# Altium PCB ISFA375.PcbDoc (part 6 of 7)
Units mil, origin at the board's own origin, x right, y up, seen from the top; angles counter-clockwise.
Board outline 5615 x 5520 mil, 6 copper layers (Top_SL, GND, POWER, Signal_Layer, GND2, Bottom_SL), stack 60.472 mil thick; 494 components, 307 nets, 1648 pads, 755 vias.
Unrouted connection lines stored in the file: 315.
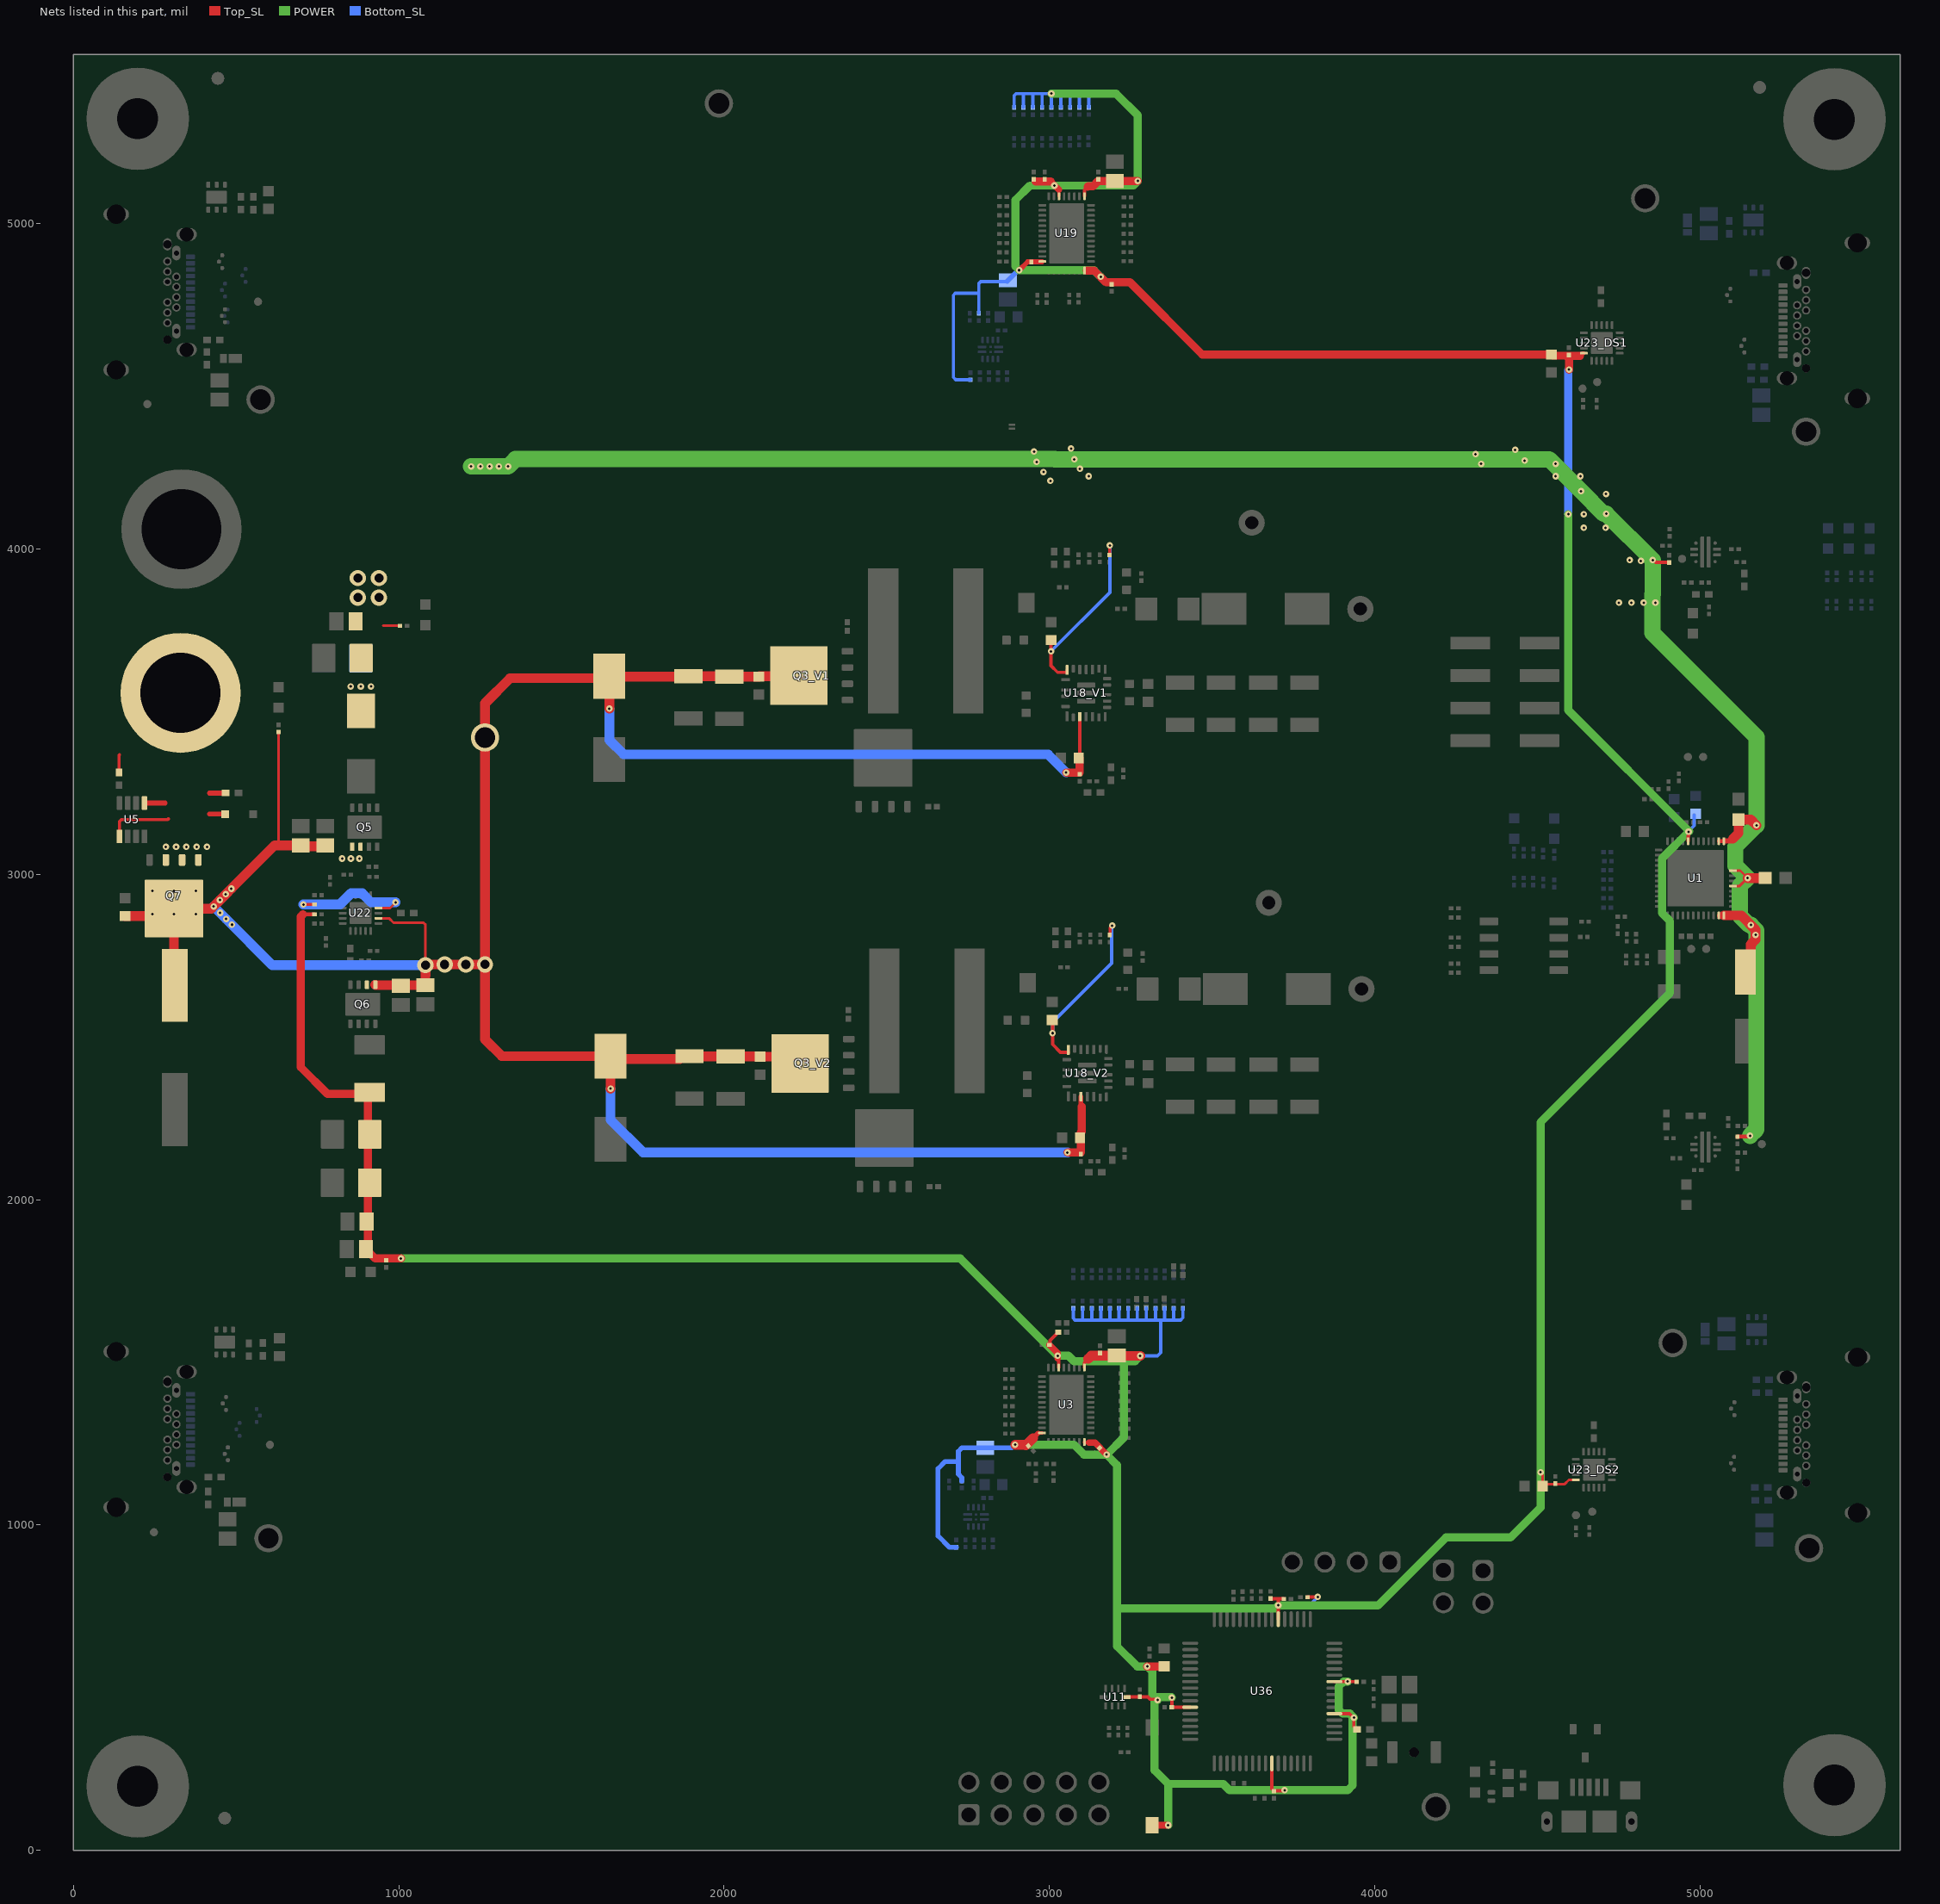
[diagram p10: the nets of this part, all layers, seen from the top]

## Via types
v1: diameter 20, hole 8, Top_SL to Bottom_SL, 628 vias
v2: diameter 19.68, hole 7.87, Top_SL to Bottom_SL, 66 vias
v3: diameter 16, hole 8, Top_SL to Bottom_SL, 23 vias
v4: diameter 16, hole 6, Top_SL to Bottom_SL, tented both sides, 16 vias
v5: diameter 137.8, hole 125.98, Top_SL to Bottom_SL, 8 vias
v6: diameter 50, hole 28, Top_SL to Bottom_SL, 8 vias
v7: diameter 28, hole 16, Top_SL to Bottom_SL, 6 vias

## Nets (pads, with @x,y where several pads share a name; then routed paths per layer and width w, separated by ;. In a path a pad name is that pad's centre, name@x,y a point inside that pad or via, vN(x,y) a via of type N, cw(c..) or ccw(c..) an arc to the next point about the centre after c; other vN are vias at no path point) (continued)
VCC_3.3V: C4.1 C13.1 C14.1 C15.1 C16.1 C17.1 C36.1 C59.1 C60.1 C61.1 C62.1 C63.1 C92.1 C93.1 C96.1 C97.1 C105.1 C106.1 C107.1 C116.1 C122_DS1.1 C122_DS2.1 L4_USB1.1 L4_USB2.1 L8.2 R23.2 R29.2 R33.2 R34.2 R35.2 R36.2 R37.2 R38.2 R39.2 R40.2 R41.2 R42.2 R43.2 R44.2 R50.2 R78.1 R79.2 R80.2 R81.2 R82.2 R83.2 R84.2 R85.2 R86.2 R87.2 R90_USB1.2 R90_USB2.2 R103_USB1.1 R103_USB2.1 R116.2 R125.2 R126.2 R127.1 R163_DS1.1 R163_DS2.1 S1.1 U1.32 U3.1 U3.6 U3.20 U3.28 U11.10 U19.1 U19.6 U19.20 U19.28 U23_DS1.10 U23_DS2.10 U36.11 U36.26 U36.37 U36.42 U36.54 | length 19780
  Top_SL w6: U19.20@2977.23,4882.9 U19.20@2978.16,4883.83
  Top_SL w8: v1(4509.98,1162.44) 4509.98,1159.19 4515.89,1153.29 C122_DS2.1@4515.89,1119.81 4522.19,1126.11 R163_DS2.1@4554.97,1126.11 ; R163_DS2.1@4554.97,1127.49 4556.35,1126.11 4584.11,1126.11 4596.83,1138.83 U23_DS2.10@4618.56,1138.83
  Top_SL w10: U3.20@2965.9,1282.43 2966.59,1283.12 U3.20@2977.43,1283.12 ; C14.1@3000.14,1553.59 3000.28,1553.59 3001.77,1555.08 3001.77,1567.58 3023.13,1588.94 3023.13,1589.73 3026.4,1593 R37.2@3027.19,1593 ; v1@3025.36,1512.36 3028.61,1509.11 U3.6@3028.61,1483.91 ; U19.6@3029.35,5084.62 3029.35,5104.68 ; U3.28@3107.35,1255.56 3107.35,1254.13 3108.42,1253.06 3121.5,1253.06 ; U3.1@3107.35,1483.91 3107.35,1499.23 3119.17,1511.04 ; U19.1@3108.09,5084.62 3108.09,5103.95 3117.89,5113.76 ; U11.10@3237.44,470.96 3238.08,471.6 3277.16,471.6 C116.1@3277.8,472.24 3278.12,471.92 3302.69,471.92 3310.34,464.27 3330.78,464.27 v1(3332.69,462.36) ; v1(3376.32,469.51) C107.1@3376.32,439.98 U36.11@3432.9,439.98 ; U36.26@3683.89,267.74 3683.89,189.18 3690.21,182.86 C106.1@3690.21,182.24 ; C105.1@3684.99,771.75 3680.86,771.75 3679.56,773.05 C105.1@3679.56,773.84 3703.57,773.83 ; C106.1@3690.21,182.07 C106.1@3690.21,182.24 ; U36.54@3703.57,710.65 3703.57,773.83 ; R126.2@3720.83,772.86 3719.86,773.83 3703.57,773.83 ; v1(3723.26,185) 3721.79,183.54 3691.51,183.54 C106.1@3690.21,182.24 ; R125.2@3793.41,778.37 3793.71,778.66 3824.56,778.66 v1(3824.85,778.96) ; U36.37@3875.82,420.3 3922.61,420.3 3935.04,407.86 v1(3935.83,407.86) 3935.83,379.9 3943.66,372.07 R127.1@3945.63,372.07 ; U36.42@3875.82,518.72 3875.89,518.8 3916.8,518.8 v1(3917,519) 3917.34,518.66 3944.06,518.66 C36.1@3944.4,518.32 ; U1.32@4963.38,3102.17 4963.38,3117.14 4964.72,3118.48 4964.72,3130.81 v1(4964.78,3130.88)
  Top_SL w12: 705.64,2877.58 R23.2@740.59,2877.58 ; 4631.23,4594 4639.1,4601.88 U23_DS1.10@4642.85,4601.88
  Top_SL w15: v1(2907.3,4857.23) 2932.97,4882.9 U19.20@2977.23,4882.9 ; 2949.9,1267.12 2965.21,1282.43 U3.20@2965.9,1282.43
  Top_SL w20: C14.1@3000.14,1553.59 3025.36,1528.37 v1(3025.36,1520.37) v1@3025.36,1512.36 ; 3004.06,5129.97 3029.35,5104.68 ; 3121.5,1253.06 3140.18,1253.06 v1@3176.35,1216.89 ; S1.1@3316.08,77.38 v1(3365.29,77.38)
  Top_SL w25: 705.64,2877.58 698.61,2870.55 698.61,2407.39 780.95,2325.05 905.28,2325.05 905.28,1854.17 C97.1@899.14,1848.03 927.68,1819.49 v1(1006.61,1819.49) ; C60.1@2957.4,5129.97 3004.06,5129.97 ; 3115,4856 3137.94,4856 3174.19,4819.75 3248,4819.75 3470.01,4597.74 C122_DS1.1@4543.49,4597.74 4546.73,4594.49 4587,4594.49 4587.49,4594 R163_DS1.1@4597.08,4594 ; 3117.89,5113.76 3119.21,5115.07 3133.61,5115.07 3150.01,5131.47 C59.1@3201.31,5131.47 v1(3271.79,5131.47) ; v1(3300.75,565.57) R29.2@3352.89,565.57 ; v1(4597.08,4551.65) R163_DS1.1@4597.08,4594 ; 4631.23,4594 R163_DS1.1@4597.08,4594
  Top_SL w30: v1(2894.65,1247) 2924.91,1247 ; C16.1@2927.34,1244.57 2949.9,1267.12 ; 3119.17,1511.04 3128.86,1520.74 3207.1,1520.74 3207.86,1519.98 v1(3279.22,1519.98)
  POWER w25: v1(1006.61,1819.49) 2726.24,1819.49 v1(3025.36,1520.37) 3058.69,1520.37 3075.11,1503.95 3229.28,1503.95 ; v1(2894.65,1247) 3075.6,1247 3106.29,1216.31 v1(3175.99,1216.31) ; v1(3006.06,5400) 3204.84,5400 3271.79,5333.05 v1(3271.79,5131.47) 3257.64,5117.32 v1@3017.6,5117.32 ; v1(3015.35,5117.32) 2940,5117.32 2895.58,5072.91 2895.58,4868.95 v1(2907.3,4857.23) 3137.39,4857.23 v1(3157.71,4836.91) ; v1(3279.22,1519.98) 3263.19,1503.95 3229.28,1503.95 ; v1@3323.45,462.36 3323.45,246.36 3365.29,204.52 ; v1(3332.69,462.36) 3324.49,470.55 ; v1(3365.29,77.38) 3365.29,204.52 ; v1(3376.32,469.51) 3375.28,470.55 3324.49,470.55 ; v1(3917,519) 3904.36,519 3889.6,504.24 3889.6,432.01 3901.31,420.3 3923.39,420.3 v1(3935.83,407.86) 3931.8,403.83 3931.8,199.65 3917.15,185 v1(3723.26,185) 3554.03,185 3534.52,204.52 3365.29,204.52 ; v1(4595.31,4107.18) 4595.31,3504.04 4966.63,3132.72 4882.89,3048.98 4882.89,2881.17 4907.52,2856.54 4907.52,2636.06 4509.98,2238.53 v1(4509.98,1162.44) 4509.98,1054.15 4417.74,961.91 4219.19,961.91 4010.46,753.17 v1(3703.57,753.17) 3693.93,743.52 3208.04,743.52 ; v1(3175.99,1216.31) 3229.28,1269.6 3229.28,1503.95 ; v1(3175.99,1216.31) 3208.04,1184.26 3208.04,743.52 ; 3208.04,743.52 3208.04,627.4 3269.87,565.57 v1(3300.75,565.57) 3316.72,549.6 3316.72,478.33 3324.49,470.55
  Bottom_SL w10: R90_USB1.2@2757.5,4520.59 2712.27,4520.59 2705,4527.86 2705,4780.28 2710.86,4786.13 2783.27,4786.13 ; R103_USB1.1@2783.27,4724.65 2783.27,4786.13 ; L4_USB1.1@2871.98,4822.39 2789.13,4822.39 2783.27,4816.53 2783.27,4786.13 ; R80.2@2891.67,5357.36 2891.67,5394.14 2897.53,5400 2920.33,5400 ; R87.2@2920.33,5357.69 2920.33,5400 ; R85.2@2948.99,5357.36 2948.99,5400 ; R79.2@2977.65,5357.36 2977.65,5399.88 2977.53,5400 ; R86.2@3006.31,5357.36 3006.19,5357.49 3006.19,5399.88 v1(3006.06,5400) ; R82.2@3034.97,5357.36 3034.97,5399.02 3035.95,5400 ; R84.2@3063.63,5357.69 3063.63,5399.69 3063.32,5400 ; R35.2@3073.26,1666.3 3073.26,1635.86 3079.12,1630 3104.63,1630 ; R81.2@3092.29,5357.69 3092.29,5396.92 3089.21,5400 ; R34.2@3101.81,1666.3 3101.81,1632.82 3104.63,1630 ; R83.2@3120.95,5357.69 3120.95,5394.14 3115.09,5400 3089.21,5400 ; R50.2@3130.14,1666.57 3130.14,1630 ; R43.2@3158.14,1666.57 3158.14,1630 ; R40.2@3186.14,1666.57 3186.14,1632.13 3188.27,1630 ; R33.2@3214.11,1666.84 3214.11,1630.18 3213.93,1630 ; R37.2@3242.14,1666.57 3242.14,1630.39 3241.75,1630 ; R36.2@3270.14,1666.57 3270.14,1630.97 3269.18,1630 ; v1(3279.22,1519.98) 3332.05,1519.98 3342.07,1530 3342.07,1630 ; R42.2@3298.14,1666.84 3298.14,1631.66 3299.8,1630 ; R44.2@3326.14,1666.57 3326.14,1631.38 3324.77,1630 ; R38.2@3354.14,1666.57 3354.14,1630 ; R41.2@3382.14,1666.57 3382.14,1630.19 3381.95,1630 ; R39.2@3410.14,1666.57 3410.14,1637 3403.14,1630 3381.95,1630 ; v1(3703.57,753.17) 3799.06,753.17 v1(3824.85,778.96) ; v1(4964.78,3130.88) 4964.78,3132.85 4981.71,3149.77 C4.1@4981.71,3183.02 ; 2920.33,5400 2948.99,5400 ; 2948.99,5400 2977.53,5400 ; 2977.53,5400 v1(3006.06,5400) ; v1(3006.06,5400) 3035.95,5400 ; 3035.95,5400 3063.32,5400 ; 3063.32,5400 3089.21,5400 ; 3104.63,1630 3130.14,1630 ; 3130.14,1630 3158.14,1630 ; 3158.14,1630 3188.27,1630 ; 3188.27,1630 3213.93,1630 ; 3213.93,1630 3241.75,1630 ; 3241.75,1630 3269.18,1630 ; 3269.18,1630 3299.8,1630 ; 3299.8,1630 3324.77,1630 ; 3324.77,1630 3342.07,1630 ; 3342.07,1630 3354.14,1630 ; 3354.14,1630 3381.95,1630
  Bottom_SL w15: R90_USB2.2@2713.5,931.89 2692.19,931.89 2657.68,966.41 2657.68,1173.67 2679.23,1195.23 2720,1195.23 ; R103_USB2.1@2730.93,1135.95 2730.93,1145.67 2720,1156.6 2720,1195.23 ; L4_USB2.1@2802.7,1237.83 2884.13,1237.83 2893.3,1247 v1(2894.65,1247) ; L4_USB2.1@2803,1237.53 2730.93,1237.53 2720,1226.6 2720,1195.23 ; L4_USB1.1@2870.05,4822.69 2903.64,4856.27 2906.34,4856.27 v1(2907.3,4857.23)
  Bottom_SL w25: v1(4595.31,4107.18) 4595.31,4549.88 v1(4597.08,4551.65)
VCC_5V: C10.1 C11.1 C86.1 C90.1 C91.1 C94.1 C95.1 L6.1 R16.2 R106.1 R115.2 R169.1 U1.11 U1.12 U1.17 U1.20 U1.25 U1.26 U22.14 | length 6906.1
  Top_SL w8: U22.14@937.59,2896.69 972.91,2896.69 v1(990.24,2914.02) ; 951.55,3764.22 R115.2@1006.55,3764.22 ; U1.17@5101.17,2964.38 U1.17@5101.17,2964.38 5121.93,2964.44 v1(5146.36,2988.87) 5123.6,3011.62 U1.20@5101.17,3011.62
  Top_SL w10: v1(706.86,2907.52) R16.2@740.68,2907.52 ; v1(4854.5,3966.01) 4857.21,3966.01 4864.24,3958.98 R106.1@4905,3958.98
  Top_SL w11: U1.26@5057.77,3102.16 U1.25@5073.52,3102.16
  Top_SL w12: R169.1@5115.54,2193.26 5115.54,2194.89 5152.05,2194.92 v1(5153.58,2196.45)
  Top_SL w15: U1.25@5073.52,3102.16 5074.52,3103.16 5094.73,3103.16 5100.14,3108.56
  Top_SL w20: 5062.2,2873.71 U1.12@5073.52,2873.71
  Top_SL w25: 5100.14,3108.56 5101.13,3109.55
  Top_SL w30: U1.12@5073.61,2873.83 5126.78,2873.83 5170.84,2829.77 5170.84,2799.47 5156.16,2784.79 5156.16,2716.41 C10.1@5139.66,2699.92 ; 5101.13,3109.55 5118.28,3126.71 5118.28,3167.92 C86.1@5118.69,3168.33 5156.23,3168.33 v1(5173.82,3150.73) ; v1(5146.36,2988.87) C11.1@5200.37,2988.87
  POWER w50: v1(1222.12,4254) v1(1250.56,4254) v1(1279,4254) v1(1307.44,4254) v1(1335.88,4254) 1358.46,4276.58 2757,4276.58 2866.61,4276.58 2867.03,4277 2966.23,4277 ; 2973.46,4276.58 3016.42,4276.58 3017,4276 4431.64,4276 4536.4,4276 4572.34,4240.06 v1(4634.5,4177.9) 4703.84,4108.56 v1(4711.95,4108.56) v1(4854.5,3966.01) 4854.5,3861.25 4853.98,3860.72 4853.98,3834.96 4853.98,3741.79 5173.82,3421.95 v1(5173.82,3150.73) ; v1@5151.19,2844.37 5121.9,2873.66 5121.9,2964.41 v1(5146.36,2988.87) 5108.4,3026.82 5108.4,3085.99 v1@5173.49,3151.07 ; v1(5153.58,2196.45) 5173.31,2216.18 5173.31,2827.29 v1(5156.23,2844.37)
  Bottom_SL w30: v1(706.86,2907.52) 819.04,2907.52 853.49,2941.97 887.32,2941.97 915.27,2914.02 v1(990.24,2914.02)
  other v1: 5170.84,2814.05 852,3578 883.15,3578 914.76,3578 4750.95,3834.96 4788.97,3834.96 4826.73,3834.96 4862.84,3834.96 4818.52,3963.35 4783.94,3966.01 4642.85,4065.54 4709.78,4065.54 4642.85,4107.18 4710.93,4169.55 3003.26,4210 3120.89,4224 4556.28,4224 4632.02,4224 2982,4237 3094,4247 4327.36,4262.02 4556.28,4262.02 2960.55,4268.14 4461,4272 3076.59,4276 4310,4292 2953,4300 4431.64,4305.03 3066.75,4309
  other v6: 874.24,3851 939,3851 874.24,3911 939,3911
VCC_IN: C20.1 C23.1 C40_V1.1 C40_V2.1 C41_V1.1 C41_V2.1 C42_V1.1 C42_V2.1 C43_V1.1 C43_V2.1 C45_V1.1 C45_V2.1 C65.1 C66.1 C101.1 C103.1 Q3_V1.5 Q3_V1.6 Q3_V1.7 Q3_V1.8 Q3_V1.9@2229.68,3611 Q3_V2.5 Q3_V2.6 Q3_V2.7 Q3_V2.8 Q3_V2.9@2233.47,2419 Q5.1 Q5.2 Q6.1 Q6.2 Q7.5 Q7.6 Q7.7 Q7.8 Q7.9@308.84,2894.98 R68_V1.2 R68_V2.2 R114.2 TP19.1 U18_V1.3 U18_V2.3 U22.12 | length 9450.9
  Top_SL w8: C103.1@157.94,2873.07 C103.1@158.92,2872.09 ; 618.28,3089.29 630,3101.01 R114.2@630,3437.98 ; U22.12@937.59,2865.2 969.86,2865.2 983.54,2851.52 1076.05,2851.52 1082.02,2845.55 v6(1082.02,2721.08)
  Top_SL w10: C45_V1.1@3093.17,3358.01 U18_V1.3@3093.17,3485.01
  Top_SL w15: U18_V2.3@3096.69,2316.85 3096.69,2288.72 3099.08,2286.32
  Top_SL w25: v1(3051.44,3313.17) 3093.15,3313.17 C45_V1.1@3093.15,3357.99 ; v1(3055.23,2145.17) 3096.94,2145.17 C45_V2.1@3096.94,2189.99 ; C45_V2.1@3093.94,2190.01 3097.19,2193.26 3097.19,2207 3099.08,2208.89 3099.08,2286.32
  Top_SL w30: C103.1@158.92,2872.09 236.42,2872.09 v1(241.91,2877.58) 251.54,2887.2 Q7.9@301.06,2887.2 ; Q7.9@308.84,2894.98 v1(308.84,2877.58) 308.84,2661.81 C101.1@311.61,2659.03 ; Q7.9@316.61,2887.2 375.77,2887.2 383.07,2894.51 423.5,2894.51 v1(430.61,2901.61) v1(450,2921) v1(468,2939) v1(485,2956) 618.28,3089.29 C66.1@698.61,3089.29 ; C66.1@689.37,3085.95 759.71,3085.95 C65.1@760.7,3084.97 ; Q6.1@927.55,2660.73 928.72,2659.56 C20.1@1081.61,2659.56 ; 1081.61,2689.98 C20.1@1081.61,2659.56 ; 1082.02,2689.98 v6(1082.02,2721.08) 1083.93,2723 v6(1141,2723) v6(1206,2723) 1206.28,2723.28 v6(1265,2723.28) ; C20.1@1087.51,2659.56 C20.1@1081.61,2659.56 ; v1(1647.13,3509.42) C43_V1.1@1647.13,3603.12 ; C43_V1.1@1649.91,3603.12 C43_V1.1@1647.13,3603.12 ; v1(1650.91,2341.42) C43_V2.1@1650.91,2441.12 ; C40_V1.1@1890.13,3608.17 1648.08,3608.17 C43_V1.1@1647.13,3609.12 C43_V1.1@1647.13,3603.12 ; C40_V1.1@1890.13,3609.13 C41_V1.1@2015.13,3609.13 ; C40_V2.1@1893.91,2440.17 C42_V2.1@2110.91,2440.17 ; C40_V2.1@1893.91,2441.13 1872.26,2441.13 1863.42,2432.29 1659.74,2432.29 C43_V2.1@1650.91,2441.12 ; C41_V1.1@2016.13,3608.17 C42_V1.1@2107.13,3608.17 ; C42_V1.1@2108.53,3609.13 2238.44,3609.13 Q3_V1.9@2240.8,3611.49 ; C42_V2.1@2111.66,2438.98 C42_V2.1@2110.91,2439.73 2212.75,2439.73 Q3_V2.9@2233.47,2419 ; v6(1265,2723.28) TP19.1@1265,3420.76 1265,3526 1342.12,3603.12 C43_V1.1@1647.13,3603.12 ; v6(1265,2723.28) 1265,2493 1316.88,2441.12 C43_V2.1@1650.91,2441.12
  Bottom_SL w30: v1(430.61,2901.61) 469.08,2863.14 610.92,2721.31 1077.75,2721.31 v6@1081.61,2717.45 ; v1(1647.13,3509.42) 1647.13,3413.17 1691.46,3368.84 2995.77,3368.84 v1(3051.44,3313.17) ; v1(1650.91,2341.42) 1650.91,2245.17 1750.91,2145.17 v1(3055.23,2145.17)
  other v1: 486.91,2845.54 469.19,2863.26 375.77,2877.58 450.49,2881.96 241.91,2949.51 308.84,2949.51 375.77,2949.51 825.82,3048.72 852.73,3048.72 878.74,3048.72
VCC_TPS55288_V1: C56_V1.1 R71_V1.2 U18_V1.19 | length 573.7
  Top_SL w10: C56_V1.1@3004.92,3720.44 v1(3004.92,3685.84) 3004.92,3641.85 3025.44,3621.33 3053.73,3621.33 3054.3,3621.9 U18_V1.19@3054.3,3628.71 ; R71_V1.2@3184.46,3981.86 3185.19,3982.6 3185.19,4010.43 v1(3185.93,4011.17)
  Bottom_SL w10: v1(3004.92,3685.84) 3185.93,3866.85 v1(3185.93,4011.17)
VCC_TPS55288_V2: C56_V2.1 R71_V2.2 U18_V2.19 | length 577.8
  Top_SL w10: C56_V2.1@3009.83,2558.68 v1(3009.83,2511.99) 3009.83,2477.63 3034.13,2453.33 3057.51,2453.33 U18_V2.19@3058.08,2453.9 ; R71_V2.2@3185.54,2814.02 3186.84,2815.32 3186.84,2835.74 3192.91,2841.81 v1(3192.91,2842.65)
  Bottom_SL w10: v1(3009.83,2511.99) 3009.83,2545.55 3191.56,2727.28 3191.56,2841.3 v1(3192.91,2842.65)
vin: C102.1 C104.1 D9.2 J4.1 Q7.1 Q7.2 Q7.3 U5.1 U5.5 | length 413.2
  Top_SL w10: C104.1@140.22,3313.69 140.22,3366.78 141.2,3367.77 ; U5.5@141.2,3117.06 141.2,3162.38 147.06,3168.24 289.64,3168.24 291.61,3170.2
  Top_SL w15: U5.1@217.98,3219.42 281.28,3219.42 ; 418.26,3185.39 D9.2@465.69,3185.39 ; 418.26,3250 C102.1@467.31,3250
  other v1: 283.84,3084.97 315.39,3084.97 346.94,3084.97 378.49,3084.97 410.03,3084.97
pads on no net: D19.1S D19.2S FID1.1 FID2.1 FID3.1 FID4.1 FID5.1 FID6.1 H1.1 H2.1 H3.1 H4.1 J7.4 J8_US1. J8_US2. J9_DS1. J9_DS2. J10.4 J10.5 J10.6 J10.7 J10.8 J10.9 Q3_V1.9@2214.13,3553.91 Q3_V1.9@2214.13,3611 Q3_V1.9@2214.13,3668.09 Q3_V1.9@2247.6,3611 Q3_V1.9@2284.21,3553.91 Q3_V1.9@2284.21,3611 Q3_V1.9@2284.21,3668.09 Q3_V2.9@2217.92,2361.91 Q3_V2.9@2217.92,2419 Q3_V2.9@2217.92,2476.09 Q3_V2.9@2251.39,2419 Q3_V2.9@2288,2361.91 Q3_V2.9@2288,2419 Q3_V2.9@2288,2476.09 Q4_V1.9@2431.75,3303.48 Q4_V1.9@2431.75,3373.56 Q4_V1.9@2488.83,3303.48 Q4_V1.9@2488.83,3340.1 Q4_V1.9@2488.83,3373.56 Q4_V1.9@2545.92,3303.48 Q4_V1.9@2545.92,3373.56 Q4_V2.9@2435.54,2135.48 Q4_V2.9@2435.54,2205.56 Q4_V2.9@2492.62,2135.48 Q4_V2.9@2492.62,2172.1 Q4_V2.9@2492.62,2205.56 Q4_V2.9@2549.71,2135.48 Q4_V2.9@2549.71,2205.56 Q5.9@828.18,3121.78 Q5.9@828.18,3168.24 Q5.9@867.75,3145.01 Q5.9@922.47,3145.01 Q5.9@962.04,3121.78 Q5.9@962.04,3168.24 Q6.9@822.24,2577.46 Q6.9@822.24,2623.92 Q6.9@861.8,2600.69 Q6.9@916.53,2600.69 Q6.9@956.09,2577.46 Q6.9@956.09,2623.92 Q7.9@251.75,2879.43 Q7.9@251.75,2949.51 Q7.9@308.84,2879.43 Q7.9@308.84,2912.89 Q7.9@308.84,2949.51 Q7.9@365.92,2879.43 Q7.9@365.92,2949.51 S4. U1.4 U1.5 U1.18 U1.19 U3.32 U4_US1.1@519.08,4841 U4_US1.2@528.92,4860.69 U4_US1.3@528.92,4821.32 U4_US2.1@572.72,1336.58 U4_US2.2@562.87,1316.9 U4_US2.3@562.87,1356.27 U5.3 U5.7 U5.8 U6_DS1.1@5083.33,4781.01 U6_DS1.2@5093.17,4761.33 U6_DS1.3@5093.17,4800.7 U6_DS2.1@5095.54,1357.5 U6_DS2.2@5105.39,1337.82 U6_DS2.3@5105.39,1377.19 U7_DS1.1@5083.42,4780.98 U7_DS1.2@5093.26,4800.66 U7_DS1.3@5093.26,4761.29 U7_DS2.1@5096.08,1358 U7_DS2.2@5105.92,1377.68 U7_DS2.3@5105.92,1338.32 U8_DS1.1@5126.91,4624.27 U8_DS1.2@5136.75,4604.59 U8_DS1.3@5136.75,4643.95 U8_DS2.1@5095.08,1190 U8_DS2.2@5104.92,1170.32 U8_DS2.3@5104.92,1209.68 U9_DS1.1@5126.61,4623.98 U9_DS1.2@5136.46,4643.66 U9_DS1.3@5136.46,4604.29 U9_DS2.1@5095.08,1190 U9_DS2.2@5104.92,1209.68 U9_DS2.3@5104.92,1170.32 U10.10 U12_US1.1@447.16,4883.32 U12_US1.2@457,4903 U12_US1.3@457,4863.63 U12_US2.1@459.08,1374 U12_US2.2@468.92,1393.68 U12_US2.3@468.92,1354.32 U13_US1.1@447.16,4883.32 U13_US1.2@457,4863.63 U13_US1.3@457,4903 U13_US2.1@459.06,1373.75 U13_US2.2@468.9,1354.07 U13_US2.3@468.9,1393.43 U14_US1.1@463.62,4716.48 U14_US1.2@473.46,4736.17 U14_US1.3@473.46,4696.8 U14_US2.1@463.98,1218.66 U14_US2.2@473.82,1238.34 U14_US2.3@473.82,1198.97 U15_US1.1@455.59,4717.18 U15_US1.2@465.44,4697.5 U15_US1.3@465.44,4736.87 U15_US2.1@465.08,1219 U15_US2.2@474.92,1199.32 U15_US2.3@474.92,1238.68 U16_US1.1@456,4796 U16_US1.2@465.84,4815.69 U16_US1.3@465.84,4776.32 U16_US2.1@500.63,1294 U16_US2.2@510.47,1313.68 U16_US2.3@510.47,1274.31 U19.5 U19.7 U19.8 U19.11 U19.24 U19.25 U19.32 U21_DS1.7@5146.28,5011.61 U21_DS1.7@5181.72,5011.61 U21_DS2.7@5156.28,1600.61 U21_DS2.7@5191.72,1600.61 U22.7 U22.21@863.77,2862.24 U22.21@863.77,2899.65 U22.21@901.17,2862.24 U22.21@901.17,2899.65 U23_DS1.16 U23_DS1.17 U23_DS1.21@4679.27,4614.67 U23_DS1.21@4679.27,4652.07 U23_DS1.21@4716.67,4614.67 U23_DS1.21@4716.67,4652.07 U23_DS2.16 U23_DS2.17 U23_DS2.21@4654.98,1151.62 U23_DS2.21@4654.98,1189.02 U23_DS2.21@4692.38,1151.62 U23_DS2.21@4692.38,1189.02 U24_US1.7@422.28,5081.61 U24_US1.7@457.72,5081.61 U24_US2.7@447.28,1562.61 U24_US2.7@482.72,1562.61 U25.10 U36.1 U36.4 U36.5 U36.6 U36.7 U36.8 U36.9 U36.10 U36.13 U36.14 U36.15 U36.16 U36.17 U36.18 U36.19 U36.20 U36.21 U36.22 U36.28 U36.29 U36.30 U36.31 U36.33 U36.36 U36.45 U36.46 U36.53 U36.57 U36.58 U36.61 U36.62 U36.63 U36.64
copper on no net:
  other v1: 4746.84,3967.68
  other v5: 3416,2033 2839,2034 3416,2912 2847.75,2912.88 2850.9,3224.15 3419,3225 2854.98,4080.88 3401.64,4080.88

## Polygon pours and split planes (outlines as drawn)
GND on Top_SL "TOP_SL_GND_P149" (solid, pour order 149): 10,5510 5609,5510 5609,6 10,6.76
PA_VBUS on Top_SL "TOP_SL_PA_VBUS_P056" (solid, pour order 56): 4990,4441 5220,4441 5220,4373 5070,4373 5071,4372 5071,4060 5006,4060 4990,4076 4990,4440.95 4989.95,4441
PA_PPHV on Top_SL "TOP_SL_PA_PPHV_P057" (solid, pour order 57): 3299.42,3935 3299.42,3870.18 5007.18,3870.18 5016,3879 5016,3935 4951.04,3935
GND on Top_SL "TOP_SL_GND_P172" (solid, pour order 172): 1451,3455.23 1796.6,3455.23 1796.6,3540.82 1800,3544.23 2127.8,3544.23 2127.8,3236.45 3297.22,3228.39 3297.22,3504.98 3894.08,3509.23 3896.08,3511.23 3897.08,3510.23 3897.08,3093.23 1451,3093.23
GND on Top_SL "TOP_SL_GND_P170" (solid, pour order 170): 1451,2289 1803,2289 1803,2376 1805,2378 2134,2378 2134,2070 3270.14,2062.17 3270.14,2338.76 3867,2343 3869,2345 3870,2344 3870,1927 1451,1927
NetQ4_V2_4 on Top_SL "TOP_SL_NETQ4_V2_4_P169" (solid, pour order 169): 2549.87,2065.13 2644.87,2065.13 2644.87,2009.98 2645.77,2009.09 2550,2009.09 2550,2065
NetQ4_V1_4 on Top_SL "TOP_SL_NETQ4_V1_4_P168" (solid, pour order 168): 2545,3236 2640,3236 2640,3180.86 2640.9,3179.96 2545.13,3179.96 2545.13,3235.87
NetC47_V1_1 on Top_SL "TOP_SL_NETC47_V1_1_P167" (solid, pour order 167): 3069,3612 3151.92,3612 3151.92,3592.17 3201.6,3592.17 3201.6,3567.2 3198.55,3570.25 3077.52,3570.25 3077.52,3582 3075.98,3583.55 3069,3583.55
NetC47_V2_1 on Top_SL "TOP_SL_NETC47_V2_1_P166" (solid, pour order 166): 3073.26,2444 3156.18,2444 3156.18,2424.17 3205.86,2424.17 3205.86,2399.2 3202.81,2402.25 3081.78,2402.25 3081.78,2414 3080.24,2415.55 3073.26,2415.55
NetQ3_V2_4 on Top_SL "TOP_SL_NETQ3_V2_4_P165" (solid, pour order 165): 2351.78,2569.6 2358.4,2569.6 2405.82,2569.6 2405.82,2480 2353.82,2480
NetQ3_V1_4 on Top_SL "TOP_SL_NETQ3_V1_4_P164" (solid, pour order 164): 2348,3762.18 2348.18,3762 2400,3762 2400,3668 2348,3668 2348,3762
NetC44_V2_2 on Top_SL "TOP_SL_NETC44_V2_2_P163" (solid, pour order 163): 2409.54,2807.31 2409.54,2476.1 2351.77,2476.1 2351.78,2476.09 2351.78,2068.64 2639.78,2068.64 2637.78,2070.64 2637.78,2806.64 2408.78,2806.64
NetC44_V1_2 on Top_SL "TOP_SL_NETC44_V1_2_P162" (solid, pour order 162): 2405.76,3986.66 2405.76,3655.45 2347.99,3655.45 2348,3655.44 2348,3248 2636,3248 2634,3250 2634,3986 2405,3986
GND on Top_SL "TOP_SL_GND_P159" (solid, pour order 159): 2900,2657 2971,2657 2971,2581 2900,2581
GND on Top_SL "TOP_SL_GND_P155" (solid, pour order 155): 2894,3826 2965,3826 2965,3750 2894,3750
NetC46_V2_2 on Top_SL "TOP_SL_NETC46_V2_2_P053" (solid, pour order 53): 2695.61,2782.34 2815.25,2781.97 2845.12,2632.13 2992.2,2413.56 3054.87,2413.56 3054.87,2390.04 3054.59,2389.76 2974.23,2389.76 2941.01,2422.98 2940.74,2422.71 2815.99,2520.78 2815.99,2317.6 2695.61,2317.6
NetC46_V1_2 on Top_SL "TOP_SL_NETC46_V1_2_P052" (solid, pour order 52): 2689.71,3950.17 2817.08,3950.17 2909.02,3668.49 2980.55,3589.59 3051.84,3580.17 3051.84,3556.65 3051.56,3556.37 2971.2,3556.37 2937.98,3589.59 2937.7,3589.32 2826.43,3683.55 2826.43,3485.6 2689.71,3485.6
VCC_5V on Top_SL "TOP_SL_VCC_5V_P084" (solid, pour order 84): 5052,3120 5052,3086 5173,3086 5173,3018 5099,3018 5099,2956 5173,2956 5172,2955 5172,2889 5049,2889 5049,2845 5100,2845 5103,2842 5103,2610 5201,2610 5202,2609 5240,2609 5240,3179 5241,3180 5088,3180 5088,3123 5085,3120
NetL6_2 on Top_SL "TOP_SL_NETL6_2_P144" (solid, pour order 144): 838.76,3272.35 839.78,3271.32 839.78,3190.47 928.97,3190.47 927.55,3191.89 927.55,3272.35
PA_VBUS on Top_SL "TOP_SL_PA_VBUS_P090" (solid, pour order 90): 5107.08,3080.23 5259.93,3080.23 5259.93,3020.84 5107.08,3020.84
PA_VBUS on Top_SL "TOP_SL_PA_VBUS_P089" (solid, pour order 89): 5113.54,3079.33 5113.16,3023.42 5232.35,3023.42 5232.35,3079.33
NetC47_V2_1 on Top_SL "TOP_SL_NETC47_V2_1_P140" (solid, pour order 140): 3911.91,2390.17 3907.91,2394.17 3167.91,2394.17 3167.91,2424.17 3221.45,2424.17 3221.45,2692.17 3366.91,2692.17 3366.91,2582.35 3366.73,2582.17 3911.91,2582.17 3911.91,2399.17
NetC47_V1_1 on Top_SL "TOP_SL_NETC47_V1_1_P134" (solid, pour order 134): 3908.13,3558.17 3899.13,3567.17 3164.13,3567.17 3164.13,3592.17 3208.13,3592.17 3208.13,3610.17 3220.67,3610.17 3220.67,3860.17 3363.13,3860.17 3363.13,3750.35 3362.94,3750.17 3908.13,3750.17 3908.13,3567.17
AGND_V2 on Top_SL "TOP_SL_AGND_V2_P125" (solid, pour order 125): 3135.82,2145.17 3258.8,2145.17 3258.8,2068.28 3258.91,2068.17 3134.34,2068.17
AGND_V2 on Top_SL "TOP_SL_AGND_V2_P123" (solid, pour order 123): 3132.03,3313.17 3255.01,3313.17 3255.01,3236.28 3255.13,3236.17 3130.55,3236.17
AGND_V2 on Top_SL "TOP_SL_AGND_V2_P116" (solid, pour order 116): 3172.91,2882.17 2897.91,2882.17 2897.91,2667.17 2968.91,2667.17 2968.91,2582.17 3037.91,2582.17 3037.91,2698.17 2997.91,2698.17 2997.91,2804.17 3172.91,2804.17
AGND_V1 on Top_SL "TOP_SL_AGND_V1_P110" (solid, pour order 110): 3169.13,4050.17 2894.13,4050.17 2894.13,3835.17 2965.13,3835.17 2965.13,3750.17 3034.13,3750.17 3034.13,3866.17 2994.13,3866.17 2994.13,3972.17 3169.13,3972.17
PB_VBUS on Top_SL "TOP_SL_PB_VBUS_P087" (solid, pour order 87): 5112.4,2952.16 5112.02,2896.25 5231.22,2896.25 5231.22,2952.16
vin on Top_SL "TOP_SL_VIN_P107" (solid, pour order 107): 429,3019.99 429.01,3020 260,3020 260,3340 250,3350 120,3350 120,3768.03 119.69,3768.35 533.69,3768.35 533.69,3354.69 527,3348 429,3348 429,3022.77
VCC_IN on Top_SL "TOP_SL_VCC_IN_P068" (solid, pour order 68): 514.71,2901.61 669.43,2746.9 1011.65,2746.9 1028.25,2763.5 1335.71,2763.5 1335.71,2540 2340,2540 2340,2361.91 1302.74,2361.91 1193,2471.65 1193,2661.81 903.03,2661.81 901.96,2660.73 878.56,2684.13 590,2684.13 590,2468.09 126.44,2468.09 126.44,2901.61 128.41,2901.61 126.44,2901.61 128.41,2901.61
VCC_IN on Top_SL "TOP_SL_VCC_IN_P082" (solid, pour order 82): 192.39,2999.09 192.38,2889.77 194.95,2887.2 497.2,2887.2 642,3032 893.3,3032 893.3,3095.8 1201.39,3095.8 1201.39,2763.39 1201.5,2763.5 1335.71,2763.5 1335.71,3512.4 1335.88,3512.57 1335.88,3520.34 2327.02,3520.34 2328,3521.32 2328,3745.13 1337.25,3745.13 1335.88,3746.5 1181.98,3592.6 1181.98,3105 555.8,3105 449.8,2999 192,2999
VCC_5V on Top_SL "TOP_SL_VCC_5V_P103" (solid, pour order 103): 848.7,4321 848.7,4007.83 830.86,3420.76 1014.48,3420.76 1014.48,4140.89 1074.59,4201 4327.36,4201 5135.38,3392.98 5135.38,3145.08 5253.79,3145.08 5253.79,3664.29 4597.08,4321
PB_PPHV on Top_SL "TOP_SL_PB_PPHV_P055" (solid, pour order 55): 3301.1,2759.9 3301.24,2759.76 3301.24,2709.68 3381.89,2709.68 3382.14,2709.43 3382.14,2530.2 4019.8,2530.2 4341,2209 4415.72,2209 4416.54,2209.82 4417.36,2209 5040,2209 5040,2265 4390,2265 4061.38,2593.62 3660.38,2593.62 3660.38,2759.9
PB_VBUS on Top_SL "TOP_SL_PB_VBUS_P054" (solid, pour order 54): 5099.2,1575.77 5099.59,1575.39 5173.61,1575.39 5173.61,2081.39 5172.61,2082.39 4989.61,2082.39 4989.61,2040.39 5122.61,2040.39 5122.61,1990.39 5099.61,1990.39 5099.61,1576.18
VCC_5V on Top_SL "TOP_SL_VCC_5V_P152" (solid, pour order 152): 5052,3079.33 5052,3115 5102.37,3165.37 5190.15,3165.37 5190.15,3079.33
VCC_5V on Top_SL "TOP_SL_VCC_5V_P153" (solid, pour order 153): 5050,2893 5050,2856 5110.25,2795.75 5191,2795.75 5191,2893 5108,2893
GND on GND "GND_GND_P077" (solid, pour order 77): 10,10 10,5510 5600,5510 5600,10
AGND_V2 on GND "GND_AGND_V2_P043" (solid, pour order 43): 3213.91,2177.17 3213.91,2891.17 2898.53,2891.17 2897.91,2890.55 2897.91,2667.17 2967.91,2667.17 2967.91,2582.17 3147.91,2582.17 3147.91,2177.17 3137.91,2177.17 3137.91,2065.17 3140.91,2062.17 3257.91,2062.17 3257.91,2176.78 3257.53,2177.17
GND on GND "GND_GND_P173" (solid, pour order 173): 1451,3455.23 1796.6,3455.23 1796.6,3540.82 1800,3544.23 2127.8,3544.23 2127.8,3236.45 3297.22,3228.39 3297.22,3504.98 3894.08,3509.23 3896.08,3511.23 3897.08,3510.23 3897.08,3093.23 1451,3093.23
GND on GND "GND_GND_P171" (solid, pour order 171): 1451,2289 1803,2289 1803,2376 1805,2378 2134,2378 2134,2070 3270.14,2062.17 3270.14,2338.76 3867,2343 3869,2345 3870,2344 3870,1927 1451,1927
GND on GND "GND_GND_P160" (solid, pour order 160): 2900,2657 2971,2657 2971,2581 2900,2581
GND on GND "GND_GND_P157" (solid, pour order 157): 2894,3826 2965,3826 2965,3750 2894,3750
AGND_V1 on GND "GND_AGND_V1_P044" (solid, pour order 44): 3210.13,3345.17 3210.13,4059.17 2894.74,4059.17 2894.13,4058.55 2894.13,3835.17 2964.13,3835.17 2964.13,3750.17 3144.13,3750.17 3144.13,3345.17 3134.13,3345.17 3134.13,3233.17 3137.13,3230.17 3254.13,3230.17 3254.13,3344.78 3253.74,3345.17
GND on GND "GND_GND_P080" (solid, pour order 80): 2883.24,3827.25 2973.24,3827.25 2973.24,3750.02 2883.24,3750.02
GND on GND "GND_GND_P079" (solid, pour order 79): 2890,2660.24 2980,2660.24 2980,2583 2890,2583
GND on GND "GND_GND_P045" (solid, pour order 45): 3211.13,3550.17 3908.13,3550.17 3908.13,3160.17 1455.13,3160.17 1455.13,3484.17 1794.27,3484.17 1794.45,3483.99 1794.45,3574.85 1794.13,3575.17 2134.13,3575.17 2134.13,3231.17 2545.13,3231.17 2545.13,3179.96 2545.92,3179.17 2968.13,3179.17 2968.13,3287.17 3064.13,3287.17 3064.13,3209.17 3065.13,3208.17 3274.13,3208.17 3274.13,3361.17 3211.13,3361.17
GND on GND "GND_GND_P046" (solid, pour order 46): 3214.91,2382.17 3911.91,2382.17 3911.91,1992.17 1458.91,1992.17 1458.91,2316.17 1798.06,2316.17 1798.23,2315.99 1798.23,2406.85 1797.91,2407.17 2137.91,2407.17 2137.91,2063.17 2548.91,2063.17 2548.91,2011.96 2549.71,2011.17 2971.91,2011.17 2971.91,2119.17 3067.91,2119.17 3067.91,2041.17 3068.92,2040.17 3277.91,2040.17 3277.91,2193.17 3214.91,2193.17
VCC_5V on POWER "POWER_VCC_5V_P141" (solid, pour order 141): 10,5510 5609,5510 5609,6 10,6.76
PA_VBUS on POWER "POWER_PA_VBUS_P099" (solid, pour order 99): 4990.05,4440.95 5220.05,4440.95 5220.05,4372.95 5070.05,4372.95 5071.05,4371.95 5071.05,4059.95 5006.05,4059.95 4990.05,4075.95 4990.05,4440.91 4990,4440.95
PB_VBUS on POWER "POWER_PB_VBUS_P113" (solid, pour order 113): 5112.4,2952.16 5112.02,2896.25 5231.22,2896.25 5231.22,2952.16
PA_VBUS on POWER "POWER_PA_VBUS_P117" (solid, pour order 117): 5107.08,3080.23 5259.93,3080.23 5259.93,3020.84 5107.08,3020.84
vin on POWER "POWER_VIN_P129" (solid, pour order 129): 429,3019.99 429.01,3020 260,3020 260,3340 250,3350 120,3350 120,3768.03 119.69,3768.35 533.69,3768.35 533.69,3354.69 527,3348 429,3348 429,3022.77
VCC_5V on POWER "POWER_VCC_5V_P106" (solid, pour order 106): 5052,3120 5052,3086 5173,3086 5173,3018 5099,3018 5099,2956 5173,2956 5172,2955 5172,2889 5049,2889 5049,2845 5100,2845 5103,2842 5103,2610 5201,2610 5202,2609 5240,2609 5240,3179 5241,3180 5088,3180 5088,3123 5085,3120
VCC_3.3V on POWER "POWER_VCC_3.3V_P133" (solid, pour order 133): 3197.95,1267.69 3099,1267.69 3099,1238 3124.51,1238 3156.3,1206.21 3156.3,680.3 3220.24,616.37 3220.06,616.19 3220.06,455.34 3332.23,455.34 3332.23,428.17 3473,428.17 3470,431.17 3470,584.55 3312.37,584.55 3197.95,698.96
VCC_5V on POWER "POWER_VCC_5V_P119" (solid, pour order 119): 848.7,4321 848.7,4007.83 830.86,3420.76 1014.48,3420.76 1014.48,4140.89 1074.59,4201 4327.36,4201 5135.38,3392.98 5135.38,3145.08 5253.79,3145.08 5253.79,3664.29 4597.08,4321
PA_PPHV on POWER "POWER_PA_PPHV_P101" (solid, pour order 101): 3299.42,3935 3299.42,3870.18 5007.18,3870.18 5016,3879 5016,3935 4951.04,3935
PB_PPHV on POWER "POWER_PB_PPHV_P098" (solid, pour order 98): 3301.1,2759.9 3301.24,2759.76 3301.24,2709.68 3381.89,2709.68 3382.14,2709.43 3382.14,2530.2 4019.8,2530.2 4341,2209 4415.72,2209 4416.54,2209.82 4417.36,2209 5040,2209 5040,2265 4390,2265 4061.38,2593.62 3660.38,2593.62 3660.38,2759.9
PB_VBUS on POWER "POWER_PB_VBUS_P072" (solid, pour order 72): 5099.2,1575.77 5099.59,1575.39 5173.61,1575.39 5173.61,2081.39 5172.61,2082.39 4989.61,2082.39 4989.61,2040.39 5122.61,2040.39 5122.61,1990.39 5099.61,1990.39 5099.61,1576.18
VCC_5V on POWER "POWER_VCC_5V_P147" (solid, pour order 147): 5052,3079.33 5052,3115 5102.37,3165.37 5190.15,3165.37 5190.15,3079.33
VCC_5V on POWER "POWER_VCC_5V_P150" (solid, pour order 150): 5050,2893 5050,2856 5110.25,2795.75 5191,2795.75 5191,2893 5108,2893
GND on Bottom_SL "BOTTOM_SL_GND_P148" (solid, pour order 148): 10,6.76 10,5510 5609,5510 5609,2.76
PA_VBUS on Bottom_SL "BOTTOM_SL_PA_VBUS_P096" (solid, pour order 96): 4990.1,4440.9 5220.1,4440.9 5220.1,4372.9 5070.1,4372.9 5071.1,4371.9 5071.1,4059.9 5006.1,4059.9 4990.1,4075.9 4990.1,4440.86 4990.05,4440.91
NetC47_V2_1 on Bottom_SL "BOTTOM_SL_NETC47_V2_1_P175" (solid, pour order 175): 3229,2413 3229,2542 3228,2543 3024,2543 3024,2413 3026,2413
NetC47_V1_1 on Bottom_SL "BOTTOM_SL_NETC47_V1_1_P083" (solid, pour order 83): 3224,3580 3224,3709 3223,3710 3019,3710 3019,3580 3021,3580
PB_VBUS on Bottom_SL "BOTTOM_SL_PB_VBUS_P118" (solid, pour order 118): 5112.4,2952.16 5112.02,2896.25 5231.22,2896.25 5231.22,2952.16
PA_VBUS on Bottom_SL "BOTTOM_SL_PA_VBUS_P130" (solid, pour order 130): 5107.08,3080.23 5259.93,3080.23 5259.93,3020.84 5107.08,3020.84
VCC_5V on Bottom_SL "BOTTOM_SL_VCC_5V_P124" (solid, pour order 124): 5052,3120 5052,3086 5173,3086 5173,3018 5099,3018 5099,2956 5173,2956 5172,2955 5172,2889 5049,2889 5049,2845 5100,2845 5103,2842 5103,2610 5201,2610 5202,2609 5240,2609 5240,3179 5241,3180 5088,3180 5088,3123 5085,3120
vin on Bottom_SL "BOTTOM_SL_VIN_P142" (solid, pour order 142): 429,3019.99 429.01,3020 260,3020 260,3340 250,3350 120,3350 120,3768.03 119.69,3768.35 533.69,3768.35 533.69,3354.69 527,3348 429,3348 429,3022.77
VCC_IN on Bottom_SL "BOTTOM_SL_VCC_IN_P122" (solid, pour order 122): 514.71,2901.61 669.43,2746.9 1011.65,2746.9 1028.25,2763.5 1335.71,2763.5 1335.71,2540 2340,2540 2340,2361.91 1302.74,2361.91 1193,2471.65 1193,2661.81 903.03,2661.81 901.96,2660.73 878.56,2684.13 590,2684.13 590,2468.09 126.44,2468.09 126.44,2901.61 128.41,2901.61 126.44,2901.61 128.41,2901.61
VCC_IN on Bottom_SL "BOTTOM_SL_VCC_IN_P120" (solid, pour order 120): 192.39,2999.09 192.38,2889.77 194.95,2887.2 497.2,2887.2 642,3032 893.3,3032 893.3,3095.8 1201.39,3095.8 1201.39,2763.39 1201.5,2763.5 1335.71,2763.5 1335.71,3512.4 1335.88,3512.57 1335.88,3520.34 2327.02,3520.34 2328,3521.32 2328,3745.13 1337.25,3745.13 1335.88,3746.5 1181.98,3592.6 1181.98,3105 555.8,3105 449.8,2999 192,2999
VCC_5V on Bottom_SL "BOTTOM_SL_VCC_5V_P135" (solid, pour order 135): 848.7,4321 848.7,4007.83 830.86,3420.76 1014.48,3420.76 1014.48,4140.89 1074.59,4201 4327.36,4201 5135.38,3392.98 5135.38,3145.08 5253.79,3145.08 5253.79,3670.56 4603.35,4321
PA_PPHV on Bottom_SL "BOTTOM_SL_PA_PPHV_P109" (solid, pour order 109): 3299.42,3935 3299.42,3870.18 5007.18,3870.18 5016,3879 5016,3935 4951.04,3935
PB_PPHV on Bottom_SL "BOTTOM_SL_PB_PPHV_P088" (solid, pour order 88): 3301.1,2759.9 3301.24,2759.76 3301.24,2709.68 3381.89,2709.68 3382.14,2709.43 3382.14,2530.2 4019.8,2530.2 4341,2209 4415.72,2209 4416.54,2209.82 4417.36,2209 5040,2209 5040,2265 4390,2265 4061.38,2593.62 3660.38,2593.62 3660.38,2759.9
PB_VBUS on Bottom_SL "BOTTOM_SL_PB_VBUS_P086" (solid, pour order 86): 5099.2,1575.77 5099.59,1575.39 5173.61,1575.39 5173.61,2081.39 5172.61,2082.39 4989.61,2082.39 4989.61,2040.39 5122.61,2040.39 5122.61,1990.39 5099.61,1990.39 5099.61,1576.18
VCC_5V on Bottom_SL "BOTTOM_SL_VCC_5V_P151" (solid, pour order 151): 5052,3079.33 5052,3115 5102.37,3165.37 5190.15,3165.37 5190.15,3079.33
VCC_5V on Bottom_SL "BOTTOM_SL_VCC_5V_P174" (solid, pour order 174): 5050,2893 5050,2856 5110.25,2795.75 5191,2795.75 5191,2893 5108,2893
GND on GND2 "GND2_GND_P078" (solid, pour order 78): 10,10 10,5510 5600,5510 5600,10
GND on GND2 "GND2_GND_P161" (solid, pour order 161): 2900,2657 2971,2657 2971,2581 2900,2581
GND on GND2 "GND2_GND_P158" (solid, pour order 158): 2894,3826 2965,3826 2965,3750 2894,3750
GND on Signal_Layer "SIGNAL_LAYER_GND_P076" (solid, pour order 76): 6,6 6,5515 357,5515 359,5517 5609,5517 5609,6

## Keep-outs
Keep-Out Layer:
  text ".Layer_Name" at 248,-858.49 h30

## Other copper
Top_SL:
  pour cut-out: 2889.43,5103.95 2889.43,4864.33 2888,4862.9 2887.9,4863 2824,4863 2824,5103.95
  pour cut-out: 3196,1492 3260.43,1492 3258.91,1247.69 3260,1248 3252.21,1247.69 3195,1247.69 3195,1492
  pour cut-out: 3209,5101 3273.43,5101 3271.79,4862.9 3259,4862.9 3208,4862.9 3208,5101
  pour cut-out: 2908.43,1499.23 2908.43,1263.33 2907,1261.9 2906.9,1262 2843,1262 2843,1499.23
  text ".Layer_Name" at 248,-858.49 h30
GND:
  pour cut-out: 3234.65,1471.92 3248.83,1471.92 3248.83,1459.31 3234.65,1459.31
  pour cut-out: 3235,1443.6 3249.18,1443.6 3249.18,1430.99 3235,1430.99
  pour cut-out: 3212.96,1443.59 3227.14,1443.59 3227.14,1430.98 3212.96,1430.98
  pour cut-out: 3212.61,1471.91 3226.79,1471.91 3226.79,1459.3 3212.61,1459.3
  pour cut-out: 3235.01,1415.6 3249.19,1415.6 3249.19,1402.99 3235.01,1402.99
  pour cut-out: 3235.01,1387.6 3249.19,1387.6 3249.19,1374.99 3235.01,1374.99
  pour cut-out: 3212.96,1387.6 3227.14,1387.6 3227.14,1374.99 3212.96,1374.99
  pour cut-out: 3212.97,1415.59 3227.15,1415.59 3227.15,1402.98 3212.97,1402.98
  pour cut-out: 3235.01,1359.6 3249.19,1359.6 3249.19,1346.99 3235.01,1346.99
  pour cut-out: 3235.01,1330.59 3249.19,1330.59 3249.19,1317.98 3235.01,1317.98
  pour cut-out: 3212.98,1330.59 3227.16,1330.59 3227.16,1317.97 3212.98,1317.97
  pour cut-out: 3212.97,1359.59 3227.15,1359.59 3227.15,1346.98 3212.97,1346.98
  pour cut-out: 3235.01,1302.6 3249.19,1302.6 3249.19,1289.99 3235.01,1289.99
  pour cut-out: 3235.02,1273.99 3249.2,1273.99 3249.2,1261.38 3235.02,1261.38
  pour cut-out: 3212.97,1274.01 3227.15,1274.01 3227.15,1261.4 3212.97,1261.4
  pour cut-out: 3212.97,1302.59 3227.15,1302.59 3227.15,1289.98 3212.97,1289.98
  pour cut-out: 2879.3,1315.67 2893.48,1315.67 2893.48,1303.06 2879.3,1303.06
  pour cut-out: 2879.3,1287.67 2893.48,1287.67 2893.48,1275.06 2879.3,1275.06
  pour cut-out: 2857.25,1287.67 2871.43,1287.67 2871.43,1275.06 2857.25,1275.06
  pour cut-out: 2857.26,1315.66 2871.44,1315.66 2871.44,1303.05 2857.26,1303.05
  pour cut-out: 2879.3,1371.67 2893.48,1371.67 2893.48,1359.06 2879.3,1359.06
  pour cut-out: 2879.3,1343.67 2893.48,1343.67 2893.48,1331.06 2879.3,1331.06
  pour cut-out: 2857.25,1343.67 2871.43,1343.67 2871.43,1331.06 2857.25,1331.06
  pour cut-out: 2857.26,1371.66 2871.44,1371.66 2871.44,1359.05 2857.26,1359.05
  pour cut-out: 2879.3,1427.67 2893.48,1427.67 2893.48,1415.06 2879.3,1415.06
  pour cut-out: 2879.3,1399.67 2893.48,1399.67 2893.48,1387.06 2879.3,1387.06
  pour cut-out: 2857.25,1399.67 2871.43,1399.67 2871.43,1387.06 2857.25,1387.06
  pour cut-out: 2857.26,1427.66 2871.44,1427.66 2871.44,1415.05 2857.26,1415.05
  pour cut-out: 2879.58,1483.73 2893.76,1483.73 2893.76,1471.12 2879.58,1471.12
  pour cut-out: 2879.29,1455.66 2893.47,1455.66 2893.47,1443.06 2879.29,1443.06
  pour cut-out: 2857.25,1455.68 2871.43,1455.68 2871.43,1443.07 2857.25,1443.07
  pour cut-out: 2857.54,1483.72 2871.72,1483.72 2871.72,1471.11 2857.54,1471.11
  pour cut-out: 3243.44,4919.23 3257.62,4919.23 3257.62,4906.62 3243.44,4906.62
  pour cut-out: 3243.44,4891.23 3257.62,4891.23 3257.62,4878.62 3243.44,4878.62
  pour cut-out: 3221.39,4891.23 3235.57,4891.23 3235.57,4878.62 3221.39,4878.62
  pour cut-out: 3221.4,4919.22 3235.58,4919.22 3235.58,4906.61 3221.4,4906.61
  pour cut-out: 3243.21,4975.31 3257.39,4975.31 3257.39,4962.7 3243.21,4962.7
  pour cut-out: 3243.21,4947.31 3257.39,4947.31 3257.39,4934.7 3243.21,4934.7
  pour cut-out: 3221.19,4947.31 3235.37,4947.31 3235.37,4934.69 3221.19,4934.69
  pour cut-out: 3221.17,4975.3 3235.35,4975.3 3235.35,4962.69 3221.17,4962.69
  pour cut-out: 3243.87,5031.27 3258.05,5031.27 3258.05,5018.66 3243.87,5018.66
  pour cut-out: 3243.45,5003.24 3257.63,5003.24 3257.63,4990.64 3243.45,4990.64
  pour cut-out: 3221.41,5003.23 3235.59,5003.23 3235.59,4990.61 3221.41,4990.61
  pour cut-out: 3221.83,5031.26 3236.01,5031.26 3236.01,5018.65 3221.83,5018.65
  pour cut-out: 3243.87,5087.27 3258.05,5087.27 3258.05,5074.66 3243.87,5074.66
  pour cut-out: 3243.87,5059.27 3258.05,5059.27 3258.05,5046.66 3243.87,5046.66
  pour cut-out: 3221.82,5059.27 3236,5059.27 3236,5046.66 3221.82,5046.66
  pour cut-out: 3221.83,5087.26 3236.01,5087.26 3236.01,5074.65 3221.83,5074.65
  pour cut-out: 2861.04,4889.82 2875.22,4889.82 2875.22,4877.21 2861.04,4877.21
  pour cut-out: 2839,4889.81 2853.18,4889.81 2853.18,4877.2 2839,4877.2
  pour cut-out: 2861.48,4918.33 2875.66,4918.33 2875.66,4905.72 2861.48,4905.72
  pour cut-out: 2839.44,4918.32 2853.62,4918.32 2853.62,4905.71 2839.44,4905.71
  pour cut-out: 2861.53,4946.65 2875.71,4946.65 2875.71,4934.04 2861.53,4934.04
  pour cut-out: 2839.49,4946.64 2853.67,4946.64 2853.67,4934.03 2839.49,4934.03
  pour cut-out: 2861.53,4974.79 2875.71,4974.79 2875.71,4962.18 2861.53,4962.18
  pour cut-out: 2839.49,4974.78 2853.67,4974.78 2853.67,4962.17 2839.49,4962.17
  pour cut-out: 2861.53,5003.65 2875.71,5003.65 2875.71,4991.04 2861.53,4991.04
  pour cut-out: 2839.49,5003.64 2853.67,5003.64 2853.67,4991.03 2839.49,4991.03
  pour cut-out: 2861.53,5032.65 2875.71,5032.65 2875.71,5020.04 2861.53,5020.04
  pour cut-out: 2839.49,5032.64 2853.67,5032.64 2853.67,5020.03 2839.49,5020.03
  pour cut-out: 2839.5,5088.63 2853.68,5088.63 2853.68,5076.02 2839.5,5076.02
  pour cut-out: 2839.49,5060.64 2853.67,5060.64 2853.67,5048.03 2839.49,5048.03
  pour cut-out: 2861.54,5060.64 2875.72,5060.64 2875.72,5048.03 2861.54,5048.03
  pour cut-out: 2861.54,5088.64 2875.72,5088.64 2875.72,5076.03 2861.54,5076.03
Bottom_SL:
  text ".Layer_Name" at 248,-858.49 h30

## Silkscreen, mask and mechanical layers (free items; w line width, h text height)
Top Overlay:
  text "'.PRJ_Number'.PCB_Rev" at 3755.65,39.37 h30
  text ".Layer_Name" at 248,-858.49 h30
Bottom Overlay:
  text ".Layer_Name" at 248,-858.49 h30
Top Paste:
  text ".Layer_Name" at 248,-858.49 h30
Bottom Paste:
  text ".Layer_Name" at 248,-858.49 h30
Top Solder:
  text ".Layer_Name" at 248,-858.49 h30
  text ".Layer_Name" at 248,-858.49 h30
Bottom Solder:
  text ".Layer_Name" at 248,-858.49 h30
Drill Guide:
  text ".Layer_Name" at 248,-858.49 h30
M1 Board Outline:
  lines w10: 5615,-89.67 5615,5517 1075.89,5517 0,5521 0,0 5615,0
  text ".Layer_Name" at 248,-858.49 h30
M2 Board Dimensions:
  rectangle: -329,-275 -204,-150
  rectangle: -204,-400 171,-275
  lines w7: -329,-275 671,-275 ; -204,-400 -204,-150 ; -79,-400 -79,-150 ; 171,-400 171,-150 ; 421,-400 421,-150 ; -329,-400 671,-400 671,-150 -329,-150 -329,-400
  text ".Layer_Name" at 248,-858.49 h30
M3 3D STEP Top:
  text ".Layer_Name" at 248,-858.49 h30
M4 3D STEP Bottom:
  text ".Layer_Name" at 248,-858.49 h30
M5 Assembly Top:
  lines w5: 4866.92,2867.92 4866.92,3108.08 5107.08,3108.08 5107.08,2867.92 4866.92,2867.92
  lines w10: -621,-930.17 5979,-930.17 ; -621,-726.83 5981,-726.83 ; -621,-523.5 -621,-1133.5 3384,-1133.5 5981,-1133.5 5981,-523.5 -620.5,-523.5 -620.5,-1133.5 955,-1133.5 ; 1844,-1133.5 1844,-523.5 ; 3111,-726.83 3111,-523.5 ; 3951,-726.83 3951,-523.5 ; 4573,-1140 4573,-937.17
  lines w25: 4899.83,2848.04 4899.83,2848.59 ; 5074.66,2134.93 5074.66,2135.87
  lines w30: 3058.68,3454.88 3059.68,3454.88 ; 3064.51,2283.01 3065.51,2283.01 ; 3108.14,5124.06 3109.14,5124.06 ; 4946.25,4014.14 4948.06,4014.14 ; 5197.05,4593.65 5198.05,4593.65 ; 5197.39,1168.14 5198.39,1168.14
  text "COMPONENTS MARKED 'DNP' SHOULD NOT BE POPULATED." at 824.5,-318.5 h30
  text "ASSEMBLY VARIANT:" at 824,-434 h30
  text ".VariantName" at 1860,-434 h30
  text "PCB VIEWED FROM TOP SIDE" at -557.5,-655.67 h30
  text "BOARD #:" at 1919,-655.67 h30
  text ".PRJ_Number" at 2464.5,-655.67 h30
  text "REV:" at 3309,-655.67 h30
  text ".PCB_Rev" at 3600.5,-655.67 h30
  text "SVN REV:" at 4147,-655.67 h30
  text ".VersionControl_RevNumber" at 4653,-655.67 h30
  text "TID #:" at 1919,-859 h30
  text ".TID" at 2464.5,-859 h30
  text "PLOT NAME =" at -557.5,-1064.34 h30
  text ".plot_File_Name" at 248,-1064.34 h30
  text "GENERATED    :" at 1921,-1064.34 h30
  text ".Print_Date" at 2790.5,-1064.34 h30
  text ".Print_Time" at 3519.5,-1064.34 h30
  text "TEXAS INSTRUMENTS" at 4784,-1064.34 h30
M6 Assembly Bottom:
  lines w3.94: 5347.82,3972.59 5405.26,3972.59 5420,3957.85 5420,3939.71
  lines w10: -621.5,-727.33 5980.5,-727.33 ; -619.5,-930.67 5980.5,-930.67 ; 786.5,-1140.5 786.5,-937.67 ; 1408.5,-727.33 1408.5,-524 ; 2248.5,-727.33 2248.5,-524 ; 3515.5,-1134 3515.5,-524 ; 4404.5,-1134 5980,-1134 5980,-524 -621.5,-524 -621.5,-1134 1975.5,-1134 5980.5,-1134 5980.5,-524 ; 4458.37,3241.75 4465.44,3234.68 4465.44,3081.12 ; 4489.06,3080.68 4489.06,3241.75 ; 4515.6,3080.68 4515.6,3241.75
  lines w25: 415.63,1185.73 415.63,1186.87 ; 415.63,4681.73 415.63,4682.87 ; 2832.45,1032.35 2832.45,1033.49 ; 2879.86,4621.62 2879.86,4622.75
  text "ASSEMBLY VARIANT:" at 11059,3651 h30
  text "COMPONENTS MARKED 'DNP' SHOULD NOT BE POPULATED." at 5773,-318 h30
  text ".VariantName" at 4729,-434 h30
  text ".VersionControl_RevNumber" at 706.5,-656.17 h30
  text "SVN REV:" at 1212.5,-656.17 h30
  text ".PCB_Rev" at 1759,-656.17 h30
  text "REV:" at 2050.5,-656.17 h30
  text ".PRJ_Number" at 2895,-656.17 h30
  text "BOARD #:" at 3440.5,-656.17 h30
  text "PCB VIEWED FROM BOTTOM SIDE" at 5917,-656.17 h30
  text ".TID" at 2895,-859.5 h30
  text "TID #:" at 3440.5,-859.5 h30
  text "TEXAS INSTRUMENTS" at 575.5,-1064.84 h30
  text ".Print_Time" at 1840,-1064.84 h30
  text ".Print_Date" at 2569,-1064.84 h30
  text "GENERATED    :" at 3438.5,-1064.84 h30
  text ".plot_File_Name" at 5111.5,-1064.84 h30
  text "PLOT NAME =" at 5917,-1064.84 h30
M9 Title Sheet:
  drawing of 57 lines, arcs and shapes, not listed
  text "1" at 410.84,8036.5 h70
  text "2" at 2906.5,8036.5 h70
  text "3" at 5395.84,8036.5 h70
  text "4" at 7902.51,8036.5 h70
  text "5" at 10401.5,8036.5 h70
  text "6" at 12906.5,8036.5 h70
  text "A" at -745.5,6893.5 h70
  text "A" at 14054.5,6893.5 h70
  text "B" at -745.5,4513.5 h70
  text "B" at 14054.5,4513.5 h70
  text "C" at -745.5,2138.5 h70
  text "C" at 14054.5,2138.5 h70
  text "PROJECT TITLE:" at 11014.5,277.5 h45
  text ".PRJ_Title" at 11064.5,144.17 h70
  text "DESIGNED FOR:" at 11014.5,-23.5 h45
  text ".PRJ_Customer" at 11064.5,-163.5 h70
  text "D" at -745.5,-231.5 h70
  text "D" at 14054.5,-231.5 h70
  text "FILE NAME:" at 11014.5,-323.5 h45
  text ".PCB_File_Name_No_Path" at 11064.5,-443.5 h70
  text "Texas Instruments (TI) and/or its licensors do not warrant the accuracy or completeness of this specification" at 6045,-605.34 h45
  text "ENGINEER:" at 11014.5,-613.5 h45
  text "LAYOUT BY:" at 12519.5,-613.5 h45
  text "or any information contained therein. TI and/or its licensors do not warrant that this design will meet" at 6000.01,-718 h45
  text ".PRJ_Engineer" at 11064.5,-768.49 h70
  text ".PCB_Layout" at 12570,-768.49 h70
  text "the specifications, will be suitable for your application or fit for any particular purpose, or will operate in" at 6000.01,-830.67 h45
  text ".Layer_Name" at 248,-858.49 h60
  text "ALTIUM DESIGNER VERSION:" at 12519.5,-923.5 h45
  text "an implementation. TI and/or its licensors do not warrant that the design is production worthy. You should" at 6000.01,-943.33 h45
  text "completely validate and test your design implementation to confirm the system functionality for your application." at 6045,-1056 h45
  text ".print_Scale" at 11064.5,-1056.83 h70
  text ".Application_BuildNumber" at 12570,-1056.83 h70
  text "1" at 410.84,-1263.5 h70
  text "2" at 2906.5,-1263.5 h70
  text "3" at 5395.84,-1263.5 h70
  text "4" at 7902.51,-1263.5 h70
  text "5" at 10401.5,-1263.5 h70
  text "6" at 12906.5,-1263.5 h70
